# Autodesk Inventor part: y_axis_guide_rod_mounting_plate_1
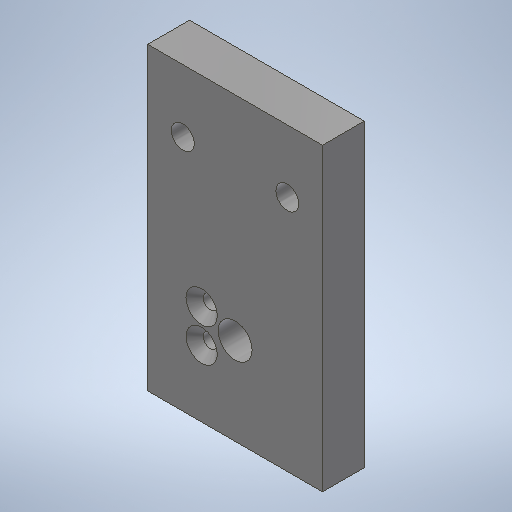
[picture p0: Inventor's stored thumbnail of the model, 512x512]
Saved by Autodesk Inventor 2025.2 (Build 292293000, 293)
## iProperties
Created: 2025-04
Part Number: y_axis_guide_rod_mounting_plate_1
Material: 1.0037 S235JR
Document SubType Name: Modeling
Designer: BennF
Density: 7.85 g/cm^3
Appearance: Stahl
Author: BennF
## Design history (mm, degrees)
sketch "Sketch2"
  geometry: L1 (20.9, 35.9)-(-20.9, 35.9); L2 (-20.9, 35.9)-(-20.9, -35.9); L3 (-20.9, -35.9)-(20.9, -35.9); L4 (20.9, -35.9)-(20.9, 35.9); 3 further points
  constraints: 8 end point, 2 midpoint, 2 parallel, 1 horizontal, 1 horizontal alignment, 1 perpendicular, 1 vertical alignment
  dimensions: "d0" = 41.8 distance of L1.start L1.end; "d1" = 71.8 distance of L3.end L1.start (computed from d0)
extrude "Extrusion1" new body sketch "Sketch2" distance "d2" = 10; taper "d3" = 0 deg
sketch "Sketch3"
  geometry: L1 (-12.5, 20.9)-(12.5, 20.9); L2 (-20.9, 35.9)-(20.9, 35.9) reference; 2 further points
  constraints: 2 end point, 1 horizontal, 1 horizontal alignment, 1 midpoint, 1 vertical alignment
  dimensions: "d11" = 25 distance of L1.start L1.end; "d12" = 15 distance between parallel lines of L2 L1
hole "Hole1" sketch "Sketch3" at (-12.5, 20.9), (12.5, 20.9) diameter "d4" = 5.5; stored, may be unused: countersink angle "d8" = 90 deg, drill point angle "d10" = 118 deg; dims "d5" = 6, "d6" = 12.5, "d7" = 2, "d9" = 8
sketch "Sketch4"
  geometry: L1 (20.9, -35.9)-(-20.9, -35.9) reference; 2 further points
  constraints: 1 vertical alignment
  dimensions: "d20" = -20.9 distance from line of L1 point (0, -15)
hole "Hole2" sketch "Sketch4" at (0, -15) diameter "d13" = 8.15; stored, may be unused: countersink angle "d17" = 90 deg, drill point angle "d19" = 118 deg; dims "d14" = 6, "d15" = 12.5, "d16" = 2, "d18" = 8
sketch "Sketch5"
  geometry: L1 (-8, 12)-(-8, 20); C1 r 4.075 at (0, 15) reference; 1 further point
  constraints: 2 end point, 1 vertical, 1 vertical alignment
  dimensions: "d28" = 8 distance of L1.start L1.end; "d29" = 8 distance from line of L1 C1.centre; "d30" = 3 vertical distance of L1.start C1.centre
hole "Hole3" sketch "Sketch5" at (-8, 12), (-8, 20) diameter "d21" = 3.4; stored, may be unused: countersink angle "d25" = 90 deg, drill point angle "d27" = 118 deg; dims "d22" = 6, "d23" = 7.5, "d24" = 2, "d26" = 8
mirror "Mirror1"
body "Solid1"
